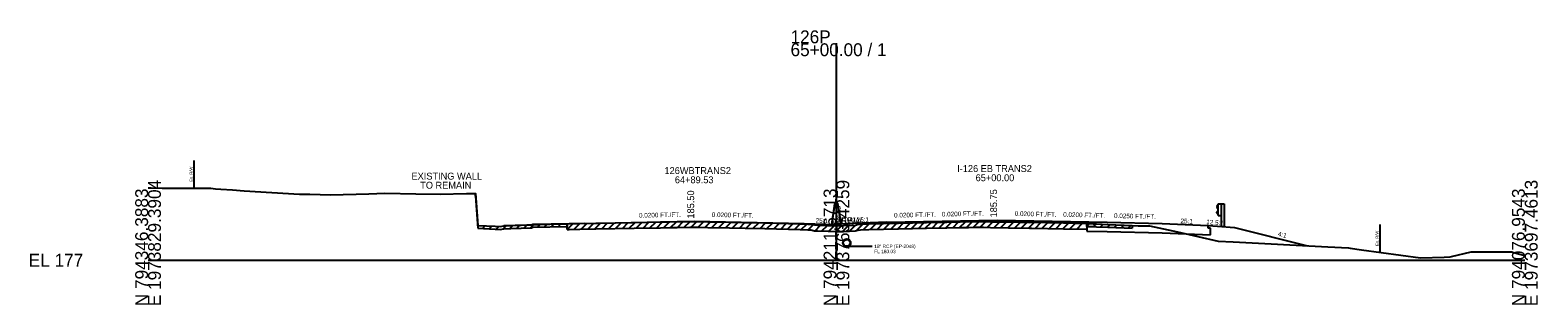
# Model space of a CAD drawing. Extents: x -161 to 1970889, y -4362 to 797231.
# Drawn here: x 2974.3 to 3302.8, y 990.3 to 1050 of the extents above; entities that cross this region are included whole.
import ezdxf

# ---------------------------------------------------------------- set-up
doc = ezdxf.new("R2010")
doc.units = 0
for name, color, linetype in [('Default', 7, 'Continuous'), ('RD_GPK_XS_Cell', 7, 'Continuous'), ('RD_XS_Base', 7, 'Continuous'), ('RD_XS_EarthShd', 7, 'Continuous'), ('RD_XS_ExGround', 7, 'Continuous'), ('RD_XS_ExPaveRet', 7, 'Continuous'), ('RD_XS_ExRW', 7, 'Continuous'), ('RD_XS_GR', 7, 'Continuous'), ('RD_XS_MedBWall', 7, 'Continuous'), ('RD_XS_Misc_Line', 7, 'Continuous'), ('RD_XS_Pave', 7, 'Continuous'), ('RD_XS_PaveOvlay', 7, 'Continuous'), ('RD_XS_PaveShd', 7, 'Continuous'), ('RD_XS_Pipe', 7, 'Continuous'), ('RD_XS_TieSlope', 7, 'Continuous'), ('RD_XS_TX_Elev_EX', 7, 'Continuous'), ('RD_XS_TX_Elev_PR', 7, 'Continuous'), ('RD_XS_TX_MkPT', 7, 'Continuous'), ('RD_XS_TX_Notes', 7, 'Continuous'), ('RD_XS_TX_Profile', 7, 'Continuous'), ('RD_XS_TX_ShdSlope', 7, 'Continuous'), ('RD_XS_TX_Slope', 7, 'Continuous'), ('RD_XS_TX_Station', 7, 'Continuous')]:
    doc.layers.add(name, color=color, linetype=linetype)

msp = doc.modelspace()

# ---------------------------------------------------------------- linework, layer by layer
at = {"layer": 'RD_GPK_XS_Cell'}
for p, q in [((3150, 1000), (3150, 1047.19)), ((3000, 1000), (3150, 1000)), ((3150, 1000), (3300, 1000))]:
    msp.add_line(p, q, dxfattribs=at)
at = {"layer": 'RD_XS_Base'}
for p, q in [((3204.54, 1006.32), (3209, 1006.23)), ((3209, 1006.23), (3221, 1005.93)), ((3221, 1005.93), (3231.51, 1005.51)), ((3231.01, 1007.01), (3231.01, 1007.57)), ((3231.51, 1006.99), (3231.01, 1007.01)), ((3231.51, 1005.51), (3231.51, 1006.99))]:
    msp.add_line(p, q, dxfattribs=at)
at = {"layer": 'RD_XS_EarthShd'}
msp.add_line((3231.01, 1007.57), (3233.01, 1007.41), dxfattribs=at)
at = {"layer": 'RD_XS_ExGround'}
msp.add_lwpolyline([(3000, 1015.73), (3000.69, 1015.73), (3003.04, 1015.71), (3004.71, 1015.71), (3006.01, 1015.7), (3007.08, 1015.69), (3008.01, 1015.69), (3008.87, 1015.68), (3009.68, 1015.68), (3012.81, 1015.66), (3013.69, 1015.64), (3014.7, 1015.56), (3015.89, 1015.45), (3018.39, 1015.3), (3020.94, 1015.13), (3033.03, 1014.4), (3035.23, 1014.35), (3039.74, 1014.23), (3048.11, 1014.47), (3051.61, 1014.57), (3058.37, 1014.46), (3063.62, 1014.38), (3069.38, 1014.51), (3070.33, 1014.54), (3071.35, 1014.54), (3071.83, 1007.59), (3075.66, 1007.4), (3076.76, 1007.34), (3077.51, 1007.46), (3079.08, 1007.53), (3083.57, 1007.71), (3083.84, 1007.82), (3091.73, 1007.96), (3094.08, 1008), (3097.58, 1008.06), (3105.92, 1008.2), (3111.68, 1008.32), (3113.69, 1008.36), (3115.3, 1008.39), (3118.08, 1008.44), (3119.71, 1008.41), (3122, 1008.38), (3126.71, 1008.3), (3130.11, 1008.23), (3134.42, 1008.13), (3142.08, 1007.94), (3143.79, 1007.87), (3144.45, 1007.85), (3145.21, 1007.67), (3145.87, 1007.65), (3148.2, 1007.56), (3150, 1007.53), (3150.59, 1007.52), (3151.12, 1007.51), (3151.54, 1007.53), (3154.15, 1007.63), (3154.71, 1007.82), (3155.25, 1007.84), (3157.08, 1007.93), (3163.51, 1008.08), (3169.64, 1008.22), (3174.07, 1008.31), (3176.96, 1008.36), (3178.77, 1008.4), (3180.39, 1008.44), (3182.08, 1008.41), (3183.57, 1008.37), (3187.47, 1008.32), (3192.08, 1008.24), (3192.55, 1008.25), (3199.51, 1008.1), (3204.93, 1007.99), (3205.94, 1007.94), (3206.67, 1007.91), (3209.14, 1007.79), (3214.46, 1007.57), (3215.73, 1007.51), (3218.19, 1007.48), (3224.34, 1006.21), (3233.15, 1004.17), (3236.48, 1003.97), (3257.05, 1002.93), (3261.56, 1002.68), (3261.92, 1002.65), (3264.43, 1002.28), (3277.3, 1000.53), (3282.44, 1000.68), (3283.7, 1000.72), (3284.02, 1000.79), (3288.33, 1001.8), (3289.07, 1001.8), (3297.19, 1001.8), (3297.52, 1001.71), (3300, 1001)], dxfattribs=at)
at = {"layer": 'RD_XS_ExPaveRet'}
for p, q in [((3071.35, 1013.91), (3071.35, 1014.54)), ((3071.35, 1013.91), (3071.83, 1006.96)), ((3071.83, 1006.96), (3075.66, 1006.77)), ((3075.66, 1006.77), (3076.76, 1006.71)), ((3076.76, 1006.71), (3077.51, 1006.84)), ((3077.51, 1006.84), (3079.08, 1006.9)), ((3079.08, 1006.9), (3083.57, 1007.08)), ((3083.57, 1007.08), (3083.84, 1007.2)), ((3083.84, 1007.2), (3091.35, 1007.32)), ((3091.35, 1006.7), (3091.35, 1007.95)), ((3091.35, 1007.95), (3091.35, 1007.32)), ((3091.35, 1006.7), (3091.73, 1006.71)), ((3091.73, 1006.71), (3094.08, 1006.75)), ((3094.08, 1006.75), (3097.58, 1006.81)), ((3097.58, 1006.81), (3105.92, 1006.95)), ((3105.92, 1006.95), (3111.68, 1007.07)), ((3111.68, 1007.07), (3113.69, 1007.11)), ((3113.69, 1007.11), (3115.3, 1007.14)), ((3115.3, 1007.14), (3118.08, 1007.19)), ((3118.08, 1007.19), (3119.71, 1007.16)), ((3119.71, 1007.16), (3122, 1007.13)), ((3122, 1007.13), (3126.71, 1007.05)), ((3126.71, 1007.05), (3130.11, 1006.98)), ((3130.11, 1006.98), (3134.42, 1006.88)), ((3134.42, 1006.88), (3142.08, 1006.69)), ((3142.08, 1006.69), (3143.79, 1006.62)), ((3143.79, 1006.62), (3144.45, 1006.6)), ((3144.45, 1006.6), (3145.21, 1006.42)), ((3145.21, 1006.42), (3145.87, 1006.4)), ((3145.87, 1006.4), (3148.2, 1006.31)), ((3148.2, 1006.31), (3150, 1006.28)), ((3150, 1006.28), (3150.59, 1006.27)), ((3150.59, 1006.27), (3151.12, 1006.26)), ((3151.12, 1006.26), (3151.54, 1006.28)), ((3151.54, 1006.28), (3154.15, 1006.38)), ((3154.15, 1006.38), (3154.71, 1006.57)), ((3154.71, 1006.57), (3155.25, 1006.59)), ((3155.25, 1006.59), (3157.08, 1006.68)), ((3157.08, 1006.68), (3163.51, 1006.83)), ((3163.51, 1006.83), (3169.64, 1006.97)), ((3169.64, 1006.97), (3174.07, 1007.06)), ((3174.07, 1007.06), (3176.96, 1007.11)), ((3176.96, 1007.11), (3178.77, 1007.15)), ((3178.77, 1007.15), (3180.39, 1007.19)), ((3180.39, 1007.19), (3182.08, 1007.16)), ((3182.08, 1007.16), (3183.57, 1007.12)), ((3183.57, 1007.12), (3187.47, 1007.07)), ((3187.47, 1007.07), (3192.08, 1006.99)), ((3192.08, 1006.99), (3192.55, 1007)), ((3192.55, 1007), (3199.51, 1006.85)), ((3199.51, 1006.85), (3204.54, 1006.75)), ((3204.54, 1008), (3204.54, 1006.75)), ((3204.54, 1007.37), (3204.54, 1008)), ((3204.54, 1007.37), (3204.93, 1007.37)), ((3204.93, 1007.37), (3205.94, 1007.31)), ((3205.94, 1007.31), (3206.67, 1007.29)), ((3206.67, 1007.29), (3209.14, 1007.17)), ((3209.14, 1007.17), (3214.46, 1006.95)), ((3214.46, 1007.57), (3214.46, 1006.95))]:
    msp.add_line(p, q, dxfattribs=at)
at = {"layer": 'RD_XS_ExRW'}
for p, q in [((3009.97, 1021.68), (3009.97, 1015.68)), ((3268.38, 1007.74), (3268.38, 1001.74))]:
    msp.add_line(p, q, dxfattribs=at)
at = {"layer": 'RD_XS_GR'}
for p, q in [((3233.16, 1012.12), (3232.89, 1011.68)), ((3233.16, 1012.29), (3233.82, 1012.29)), ((3233.16, 1009.72), (3233.16, 1012.29)), ((3233.82, 1012.29), (3234.49, 1012.29)), ((3233.82, 1012.29), (3233.82, 1007.34)), ((3234.49, 1012.29), (3234.49, 1007.23)), ((3232.89, 1011.68), (3232.89, 1011.57)), ((3232.89, 1011.57), (3233.16, 1011.13)), ((3232.89, 1010.43), (3233.16, 1010.87)), ((3232.89, 1010.32), (3232.89, 1010.43)), ((3233.16, 1009.88), (3232.89, 1010.32)), ((3233.16, 1009.72), (3233.82, 1009.72))]:
    msp.add_line(p, q, dxfattribs=at)
at = {"layer": 'RD_XS_MedBWall'}
for p, q in [((3149, 1007.73), (3149.69, 1012.38)), ((3149, 1007.76), (3149.67, 1012.24)), ((3150, 1012.24), (3149.67, 1012.24)), ((3149.69, 1012.38), (3150.33, 1012.38)), ((3151, 1007.85), (3150.33, 1012.38))]:
    msp.add_line(p, q, dxfattribs=at)
at = {"layer": 'RD_XS_Misc_Line'}
for p, q in [((3071.35, 1013.91), (3071.39, 1013.95)), ((3072.85, 1006.91), (3073.44, 1007.51)), ((3074.35, 1006.84), (3074.94, 1007.43)), ((3075.85, 1006.76), (3076.44, 1007.36)), ((3077.35, 1006.81), (3078.02, 1007.48)), ((3078.85, 1006.89), (3079.5, 1007.54)), ((3080.35, 1006.95), (3081, 1007.6)), ((3081.85, 1007.01), (3082.5, 1007.66)), ((3083.35, 1007.07), (3084.1, 1007.82)), ((3084.85, 1007.21), (3085.48, 1007.85)), ((3086.35, 1007.24), (3086.98, 1007.87)), ((3087.85, 1007.26), (3088.48, 1007.9)), ((3089.35, 1007.29), (3089.98, 1007.93)), ((3091.35, 1006.7), (3092.62, 1007.97)), ((3092.85, 1006.73), (3094.12, 1008)), ((3094.35, 1006.75), (3095.62, 1008.02)), ((3095.85, 1006.78), (3097.12, 1008.05)), ((3097.35, 1006.81), (3098.62, 1008.08)), ((3098.85, 1006.83), (3100.12, 1008.1)), ((3100.35, 1006.86), (3101.62, 1008.13)), ((3101.85, 1006.88), (3103.12, 1008.16)), ((3103.35, 1006.91), (3104.62, 1008.18)), ((3104.85, 1006.94), (3106.12, 1008.21)), ((3106.35, 1006.96), (3107.62, 1008.24)), ((3107.85, 1006.99), (3109.12, 1008.27)), ((3109.35, 1007.02), (3110.62, 1008.3)), ((3110.85, 1007.05), (3112.12, 1008.33)), ((3112.35, 1007.08), (3113.62, 1008.36)), ((3113.85, 1007.11), (3115.12, 1008.38)), ((3115.35, 1007.14), (3116.62, 1008.41)), ((3116.85, 1007.16), (3118.12, 1008.44)), ((3118.35, 1007.18), (3119.58, 1008.41)), ((3119.85, 1007.16), (3121.08, 1008.39)), ((3121.35, 1007.13), (3122.58, 1008.37)), ((3122.85, 1007.11), (3124.08, 1008.34)), ((3124.35, 1007.09), (3125.58, 1008.32)), ((3125.85, 1007.06), (3127.08, 1008.29)), ((3127.35, 1007.03), (3128.57, 1008.26)), ((3128.85, 1007.01), (3130.07, 1008.23)), ((3130.35, 1006.98), (3131.57, 1008.2)), ((3131.85, 1006.94), (3133.07, 1008.16)), ((3133.35, 1006.91), (3134.57, 1008.13)), ((3134.85, 1006.87), (3136.07, 1008.09)), ((3136.35, 1006.83), (3137.57, 1008.05)), ((3137.85, 1006.79), (3139.07, 1008.01)), ((3139.35, 1006.76), (3140.57, 1007.98)), ((3140.85, 1006.72), (3142.07, 1007.94)), ((3142.35, 1006.68), (3143.55, 1007.88)), ((3143.85, 1006.62), (3144.96, 1007.73)), ((3145.35, 1006.42), (3146.55, 1007.62)), ((3146.85, 1006.36), (3148.05, 1007.57)), ((3148.35, 1006.31), (3149.58, 1007.54)), ((3149.85, 1006.28), (3151.08, 1007.51)), ((3151.35, 1006.27), (3152.65, 1007.57)), ((3152.85, 1006.33), (3154.15, 1007.63)), ((3154.35, 1006.45), (3155.76, 1007.86)), ((3155.85, 1006.62), (3157.16, 1007.93)), ((3157.35, 1006.68), (3158.63, 1007.96)), ((3158.85, 1006.72), (3160.13, 1008)), ((3160.35, 1006.76), (3161.63, 1008.04)), ((3161.85, 1006.79), (3163.13, 1008.07)), ((3163.35, 1006.83), (3164.63, 1008.11)), ((3164.85, 1006.86), (3166.13, 1008.14)), ((3166.35, 1006.9), (3167.63, 1008.18)), ((3167.85, 1006.93), (3169.13, 1008.21)), ((3169.35, 1006.97), (3170.62, 1008.24)), ((3170.85, 1007), (3172.12, 1008.27)), ((3172.35, 1007.03), (3173.62, 1008.3)), ((3173.85, 1007.06), (3175.12, 1008.33)), ((3175.35, 1007.08), (3176.62, 1008.35)), ((3176.85, 1007.11), (3178.12, 1008.38)), ((3178.35, 1007.14), (3179.63, 1008.42)), ((3179.85, 1007.17), (3181.1, 1008.42)), ((3181.35, 1007.17), (3182.57, 1008.4)), ((3182.85, 1007.14), (3184.07, 1008.36)), ((3184.35, 1007.11), (3185.58, 1008.34)), ((3185.85, 1007.09), (3187.08, 1008.32)), ((3187.35, 1007.07), (3188.58, 1008.3)), ((3188.85, 1007.04), (3190.08, 1008.27)), ((3190.35, 1007.02), (3191.58, 1008.25)), ((3191.85, 1006.99), (3193.09, 1008.24)), ((3193.35, 1006.98), (3194.57, 1008.21)), ((3194.85, 1006.95), (3196.07, 1008.18)), ((3196.35, 1006.92), (3197.57, 1008.14)), ((3197.85, 1006.89), (3199.07, 1008.11)), ((3199.35, 1006.86), (3200.57, 1008.08)), ((3200.85, 1006.83), (3202.07, 1008.05)), ((3202.35, 1006.79), (3203.57, 1008.02)), ((3204.54, 1007.37), (3205.15, 1007.98)), ((3206.04, 1007.31), (3206.65, 1007.91)), ((3207.54, 1007.25), (3208.14, 1007.84)), ((3209.04, 1007.17), (3209.64, 1007.77)), ((3210.54, 1007.11), (3211.14, 1007.71)), ((3212.04, 1007.05), (3212.64, 1007.65)), ((3213.54, 1006.99), (3214.14, 1007.59))]:
    msp.add_line(p, q, dxfattribs=at)
at = {"layer": 'RD_XS_Pave'}
for p, q in [((3161, 1008.27), (3185, 1008.75)), ((3185, 1008.75), (3209, 1008.27)), ((3095, 1008.02), (3119, 1008.5)), ((3119, 1008.5), (3143, 1008.02)), ((3209, 1008.27), (3221, 1007.97))]:
    msp.add_line(p, q, dxfattribs=at)
at = {"layer": 'RD_XS_PaveOvlay'}
for p, q in [((3091.35, 1007.95), (3091.73, 1007.96)), ((3091.73, 1007.96), (3094.08, 1008)), ((3094.08, 1008), (3097.58, 1008.06)), ((3097.58, 1008.06), (3105.92, 1008.2)), ((3105.92, 1008.2), (3111.68, 1008.32)), ((3111.68, 1008.32), (3113.69, 1008.36)), ((3113.69, 1008.36), (3115.3, 1008.39)), ((3115.3, 1008.39), (3118.08, 1008.44)), ((3118.08, 1008.44), (3119.71, 1008.41)), ((3119.71, 1008.41), (3122, 1008.38)), ((3122, 1008.38), (3126.71, 1008.3)), ((3126.71, 1008.3), (3130.11, 1008.23)), ((3130.11, 1008.23), (3134.42, 1008.13)), ((3134.42, 1008.13), (3142.08, 1007.94)), ((3142.08, 1007.94), (3143.79, 1007.87)), ((3143.79, 1007.87), (3144.45, 1007.85)), ((3144.45, 1007.85), (3145.21, 1007.67)), ((3145.21, 1007.67), (3145.87, 1007.65)), ((3145.87, 1007.65), (3148.2, 1007.56)), ((3148.2, 1007.56), (3150, 1007.53)), ((3150, 1007.53), (3150.59, 1007.52)), ((3150.59, 1007.52), (3151.12, 1007.51)), ((3151.12, 1007.51), (3151.54, 1007.53)), ((3151.54, 1007.53), (3154.15, 1007.63)), ((3154.15, 1007.63), (3154.71, 1007.82)), ((3154.71, 1007.82), (3155.25, 1007.84)), ((3155.25, 1007.84), (3157.08, 1007.93)), ((3157.08, 1007.93), (3163.51, 1008.08)), ((3163.51, 1008.08), (3169.64, 1008.22)), ((3169.64, 1008.22), (3174.07, 1008.31)), ((3174.07, 1008.31), (3176.96, 1008.36)), ((3176.96, 1008.36), (3178.77, 1008.4)), ((3178.77, 1008.4), (3180.39, 1008.44)), ((3180.39, 1008.44), (3182.08, 1008.41)), ((3182.08, 1008.41), (3183.57, 1008.37)), ((3183.57, 1008.37), (3187.47, 1008.32)), ((3187.47, 1008.32), (3192.08, 1008.24)), ((3192.08, 1008.24), (3192.55, 1008.25)), ((3192.55, 1008.25), (3199.51, 1008.1)), ((3199.51, 1008.1), (3204.54, 1008)), ((3204.54, 1008), (3204.54, 1006.32))]:
    msp.add_line(p, q, dxfattribs=at)
msp.add_lwpolyline([(3071.87, 1007.58), (3075.66, 1007.4), (3076.76, 1007.34), (3077.51, 1007.46), (3079.08, 1007.53), (3083.57, 1007.71), (3083.84, 1007.82), (3091.35, 1007.95)], dxfattribs=at)
at = {"layer": 'RD_XS_PaveShd'}
for p, q in [((3095, 1008.02), (3077.51, 1007.46)), ((3143, 1008.02), (3150, 1007.74)), ((3161, 1008.27), (3150, 1007.83)), ((3150, 1007.69), (3150, 1007.83)), ((3221, 1007.97), (3231.01, 1007.57))]:
    msp.add_line(p, q, dxfattribs=at)
at = {"layer": 'RD_XS_Pipe'}
msp.add_line((3152.75, 1003.03), (3157.75, 1003.03), dxfattribs=at)
for radius in [0.85, 0.75]:
    msp.add_circle((3152.25, 1003.78), radius, dxfattribs=at)
at = {"layer": 'RD_XS_TieSlope'}
for p, q in [((3233.01, 1007.41), (3236.76, 1007.12)), ((3236.76, 1007.12), (3252.63, 1003.15))]:
    msp.add_line(p, q, dxfattribs=at)

# ---------------------------------------------------------------- texts
at = {"layer": 'Default'}
msp.add_text('35', height=1.5, dxfattribs=at).set_placement((3150, 1007.74))
at = {"layer": 'RD_GPK_XS_Cell'}
for s, p in [('126P', (3140, 1047.19)), ('65+00.00 / 1', (3140, 1044.39)), ('EL 177', (2974, 998.6))]:
    msp.add_text(s, height=2.8, dxfattribs=at).set_placement(p)
for s, p in [('N 794346.3883', (3000, 990)), ('E 1973829.3904', (3002.8, 990)), ('N 794211.6713', (3150, 990)), ('E 1973763.4259', (3152.8, 990)), ('N 794076.9543', (3300, 990)), ('E 1973697.4613', (3302.8, 990))]:
    msp.add_text(s, height=2.8, rotation=90, dxfattribs=at).set_placement(p)
at = {"layer": 'RD_XS_ExRW'}
for p in [(3009.72, 1017.06), (3268.13, 1003.13)]:
    msp.add_text('Ex. R/W ', height=0.65, rotation=90, dxfattribs=at).set_placement(p)
at = {"layer": 'RD_XS_Pipe'}
for s, p in [('18" RCP (EP-2048)', (3158.25, 1002.65)), ('FL 180.03', (3158.25, 1001.53))]:
    msp.add_text(s, height=0.75, dxfattribs=at).set_placement(p)
at = {"layer": 'RD_XS_TX_Elev_EX'}
msp.add_text('184.53', height=1, rotation=90, dxfattribs=at).set_placement((3151, 1007.53))
at = {"layer": 'RD_XS_TX_Elev_PR'}
for s, p in [(' 185.75', (3185, 1008.75)), (' 185.50', (3119, 1008.5))]:
    msp.add_text(s, height=1.5, rotation=90, dxfattribs=at).set_placement(p)
at = {"layer": 'RD_XS_TX_MkPT'}
for s, p in [('WBW', (3149, 1007.76)), ('EBW', (3151, 1007.85))]:
    msp.add_text(s, height=1.5, dxfattribs=at).set_placement(p)
at = {"layer": 'RD_XS_TX_Notes'}
for s, p in [('EXISTING WALL', (3057.4, 1017.54)), ('TO REMAIN', (3059.3, 1015.57))]:
    msp.add_text(s, height=1.5, dxfattribs=at).set_placement(p)
at = {"layer": 'RD_XS_TX_Profile'}
for rotation, p in [(357.7094, (3145.46, 1008.17)), (2.2906, (3154.44, 1008.26)), (357.7112, (3224.96, 1008.06))]:
    msp.add_text('25:1', height=1, rotation=rotation, dxfattribs=at).set_placement(p)
at = {"layer": 'RD_XS_TX_ShdSlope'}
msp.add_text('12.5:1', height=1, rotation=355.4297, dxfattribs=at).set_placement((3230.55, 1007.86))
at = {"layer": 'RD_XS_TX_Slope'}
for s, rotation, p in [('0.0200 FT./FT.', 1.1458, (3106.98, 1009.26)), ('0.0200 FT./FT.', 358.8542, (3122.83, 1009.42)), ('0.0200 FT./FT.', 1.1458, (3162.56, 1009.28)), ('0.0200 FT./FT.', 1.1458, (3172.98, 1009.51)), ('0.0200 FT./FT.', 358.569, (3188.84, 1009.66)), ('0.0200 FT./FT.', 358.569, (3199.4, 1009.46)), ('0.0250 FT./FT.', 358.569, (3210.47, 1009.2)), ('4:1', 345.9745, (3246.11, 1005.3))]:
    msp.add_text(s, height=1, rotation=rotation, dxfattribs=at).set_placement(p)
at = {"layer": 'RD_XS_TX_Station'}
for s, p in [('126WBTRANS2', (3112.53, 1018.75)), ('I-126 EB TRANS2', (3176.31, 1019.19)), ('65+00.00', (3180.33, 1017.19)), ('64+89.53', (3114.79, 1016.75))]:
    msp.add_text(s, height=1.5, dxfattribs=at).set_placement(p)

doc.saveas('drawing.dxf')
